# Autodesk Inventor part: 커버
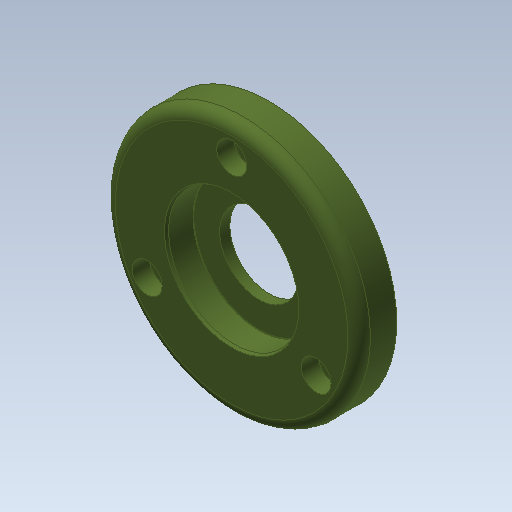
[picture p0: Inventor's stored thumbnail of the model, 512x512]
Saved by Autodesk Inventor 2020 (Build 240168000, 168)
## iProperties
Created: 2016-06
Part Number: 커버
Material: 알루미늄 6061
Document SubType Name: Modeling
Designer: mduedu
Density: 2.71 g/cm^3
Appearance: 올리브 녹색
Author: mduedu
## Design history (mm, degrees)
sketch "스케치1"
  geometry: C1 r 34 at (0, 0); 1 further point
  constraints: 1 centre point, 1 coincident
  dimensions: "d0" = 68 diameter of C1
extrude "돌출1" new body sketch "스케치1" distance "d2" = 10; taper "d3" = 0 deg
sketch "스케치2"
  geometry: C1 r 21 at (0, 0); 1 further point
  constraints: 1 centre point, 1 coincident
  dimensions: "d4" = 42 diameter of C1
extrude "돌출2" join sketch "스케치2" distance "d6" = 3; taper "d7" = 0 deg
fillet "모깎기1" dims "d8" = 3
hole "구멍1" diameter "d11" = 35; stored, may be unused: countersink angle "d15" = 90 deg, drill point angle "d17" = 0 deg; dims "d9" = 10, "d10" = 10, "d12" = 6, "d13" = 4, "d14" = 2, "d16" = 3
hole "구멍2" diameter "d20" = 35; stored, may be unused: countersink angle "d24" = 90 deg, drill point angle "d26" = 0 deg; dims "d21" = 6, "d22" = 4, "d23" = 2, "d25" = 7.3, "d73" = 10, "d74" = 10
hole "구멍3" diameter "d29" = 21; stored, may be unused: countersink angle "d33" = 90 deg, drill point angle "d35" = 0 deg; dims "d27" = 10, "d28" = 10, "d30" = 6, "d31" = 4, "d32" = 2, "d34" = 5
fillet "모깎기2" dims "d36" = 3
fillet "모깎기3" dims "d37" = 0.1
chamfer "모따기1" distance "d38" = 0.7; stored, may be unused: second distance "d39" = 2, angle "d40" = 30 deg
chamfer "모따기2" distance "d42" = 0.5; stored, may be unused: second distance "d43" = 2, angle "d44" = 30 deg
sketch "스케치5" dims "d60" = 52
  geometry: 3 further points
  constraints: 2 vertical alignment, 1 coincident, 2 other
hole "구멍5" sketch "스케치5" at (0, 26) diameter "d61" = 4.5; stored, may be unused: countersink angle "d65" = 90 deg, drill point angle "d67" = 118 deg; dims "d62" = 6, "d63" = 8, "d64" = 4.6, "d66" = 8
node "솔리드1"
pattern_circular "원형 패턴1" dims angle "d69" = 360 deg
